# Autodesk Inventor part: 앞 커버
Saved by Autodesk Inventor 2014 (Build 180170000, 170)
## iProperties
Created: 2026-06
Part Number: 앞 커버
Material: 알루미늄 6061
Document SubType Name: Modeling
Designer: dg
Density: 2.71 g/cm^3
Appearance: 알루미늄 - 평지
Mass: 41.885 g
Surface Area: 74.5404 cm^2
Volume: 15.4557 cm^3
Author: jhkim
Creation Date: 2026-05-29
Sending System: Autodesk Inventor 2027
Preprocessor: ST-DEVELOPER v20.1
Author: dg
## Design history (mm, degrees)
node "앞 커버1"
node "솔리드1"
node "기준1"
